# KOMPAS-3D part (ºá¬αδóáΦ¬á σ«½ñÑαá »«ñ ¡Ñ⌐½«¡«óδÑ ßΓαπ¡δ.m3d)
File: created 26.07.2016 11:25:23, last saved 26.07.2016 11:28:07.
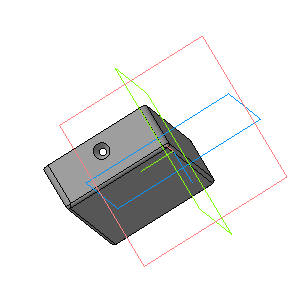
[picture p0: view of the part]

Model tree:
1. Эскиз:1
2. Операция выдавливания:1
     Расстояние 1 = 13.5
3. Эскиз:2
4. Операция выдавливания:2
     Расстояние 1 = 1
5. Скругление:1
     Радиус = 1
6. Скругление:2
     Радиус = 2
7. Скругление:3
     Радиус = 2
8. Эскиз:3
9. Вырезать элемент выдавливания:1
     Расстояние 1 = 100
10. Эскиз:4
11. Вырезать элемент выдавливания:2
     Расстояние 1 = 2; Угол 1 = 35
12. Эскиз:5
13. Вырезать элемент выдавливания:3
     Расстояние 1 = 2; Угол 1 = 35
